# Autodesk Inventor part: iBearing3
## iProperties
Length Units: 11269
Angle Units: 11279
Time Units: 11290
Mass Units: 11283
Shininess: 86.0
Angle Display Precision: 2
Document Length Units: 11269
Document Angle Units: 11279
Document Time Units: 11290
Document Mass Units: 11286
Document Length Units Precision: 3
Document Angle Units Precision: 2
Compacted: True
Created: 2000-11
Part Number: iBearing3
User Status: release
Material: Steel, High Strength Low Alloy
Document SubType Name: Modeling
Designer: Administrator
Density: 7.84
Volumn: 10.92938973139743
Area: 86.70517834789415
PropertySet Name: Model Information
Control State: 0
Master: False
Checked Out: False
Author: Administrator
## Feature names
1. Derived Body1 [Tagging]
